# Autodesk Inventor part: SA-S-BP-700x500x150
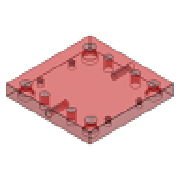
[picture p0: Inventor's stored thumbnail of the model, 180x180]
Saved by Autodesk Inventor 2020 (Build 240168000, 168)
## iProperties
Created: 2019-01
Part Number: SA-S-BP-700x500x150
Material: S 55 C
Description: Core Plate
Document SubType Name: Modeling
Designer: LENOVO-CADCIM
Standard Revision: 1
Manufacturer: FUTABA
Language: en-US
Size Designation: 700x500x150
Categories: <MemberInstance><Categories><Category DisplayName="Mold" InternalName="349578f2-f4d4-4954-8c09-8e99297a61c0" Mnemonic="MOLD"><Category DisplayName="Mold Plates"
Density: 7.85 g/cm^3
Appearance: Dark Red
IsCustomPart: 1
Author: LENOVO-CADCIM
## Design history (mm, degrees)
sketch "Sketch1"
  geometry: L1 (-250, 350)-(250, 350); L2 (250, 350)-(250, -350); L3 (250, -350)-(-250, -350); L4 (-250, -350)-(-250, 350); 7 further points
  constraints: 8 end point, 2 horizontal alignment, 2 midpoint, 2 parallel, 1 horizontal, 1 perpendicular, 1 vertical alignment
  dimensions: "d123" = 500 distance between parallel lines of L2 L4 (= W_); "d124" = 700 distance between parallel lines of L3 L1 (= L); "d125" = 317 vertical distance of point (0, 0) point (-128, 317) (= 0.5 x RP_L); "d126" = 128 horizontal distance of point (0, 0) point (-128, 317) (= 0.5 x RP_W); "d127" = 207 horizontal distance of point (0, 0) point (-207, 307) (= 0.5 x GP_W); "d128" = 307 vertical distance of point (0, 0) point (-207, 307) (= 0.5 x GP_L); "d129" = 205 horizontal distance of point (0, 0) point (-205, 243) (= 0.5 x S1_W); "d130" = 243 vertical distance of point (0, 0) point (-205, 243) (= 0.5 x S1_L); "d140" = 207 horizontal distance of point (207, 307) point (0, 0) (= 0.5 x GP_W)
extrude "Extrusion1" new body sketch "Sketch1" distance "d20" = 150 (= H_); taper "d30" = 0 deg
feature "Sculpt3"
body "Solid1"
sketch "Sketch2"
  geometry: L1 (500, 0)-(0, 0) reference; 3 further points
  constraints: 1 midpoint, 1 vertical alignment
  dimensions: "d186" = 75 distance from line of L1 point (250, 75) (= 0.5 x H_)
hole "Hole1" sketch "Sketch2" diameter "d104" = 31.67; stored, may be unused: countersink angle "d108" = 90 deg, drill point angle "d110" = 118 deg; dims "d105" = 59 (= le), "d106" = 46 (= GP_d2), "d107" = 10 (= GP_k), "d109" = 82 (= ke)
sketch "Sketch3"
  geometry: L1 (0, 0)-(500, 0) reference; 3 further points
  constraints: 1 midpoint, 1 vertical alignment
  dimensions: "d187" = 75 distance from line of point (250, -75) L1 (= 0.5 x H_)
hole "Hole2" sketch "Sketch3" diameter "d113" = 31.67; stored, may be unused: countersink angle "d117" = 90 deg, drill point angle "d119" = 118 deg; dims "d114" = 59 (= le), "d115" = 46 (= GP_d2), "d116" = 10 (= GP_k), "d118" = 82 (= ke)
hole "Hole3" sketch "Sketch1" diameter "d131" = 13.835; stored, may be unused: countersink angle "d135" = 90 deg, drill point angle "d137" = 118 deg; dims "d132" = 20 (= H_l), "d133" = 4, "d134" = 2, "d136" = 30 (= H_u)
pattern_linear "Rectangular Pattern1" dims "d164" = 243 (computed from S1_L, Ns), "d167" = 410 (computed from S1_W, Nw)
hole "Hole4" sketch "Sketch1" diameter "d141" = 40 (= GP_d1); stored, may be unused: countersink angle "d145" = 90 deg, drill point angle "d147" = 0 deg; dims "d142" = 6, "d143" = 46 (= GP_d2), "d144" = 10 (= GP_k), "d146" = 150 (= H_)
pattern_linear "Rectangular Pattern2" dims "d170" = 614 (computed from GP_L, Nl)
hole "Hole5" sketch "Sketch1" diameter "d148" = 40 (= GP_d1); stored, may be unused: countersink angle "d152" = 90 deg, drill point angle "d154" = 0 deg; dims "d149" = 6, "d150" = 46 (= GP_d2), "d151" = 10 (= GP_k), "d153" = 150 (= H_)
pattern_linear "Rectangular Pattern3" dims "d173" = 612 (computed from GP_L2, GP_L1, Nl)
hole "Hole6" sketch "Sketch1" diameter "d155" = 30 (= RP_dt); stored, may be unused: countersink angle "d159" = 90 deg, drill point angle "d161" = 0 deg; dims "d156" = 6, "d157" = 46 (= GP_d2), "d158" = 10 (= GP_k), "d160" = 150 (= H_)
pattern_linear "Rectangular Pattern4" dims "d176" = 634 (computed from RP_L, Nl), "d179" = 256 (computed from RP_W, Nw)
chamfer "Chamfer1" distance "d180" = 0.5; stored, may be unused: second distance "d181" = 2, angle "d182" = 45 deg
feature "Surface3"
body "Srf3"
other parameters: "L" = 700 [user parameter; used in 1 equation term], "W_" = 500 [user parameter; used in 3 equation terms], "H_" = 150 [user parameter; used in 8 equation terms], "GP_W" = 414 [user parameter; used in 2 equation terms], "GP_d1" = 40 [user parameter; used in 2 equation terms], "GP_d2" = 46 [user parameter; used in 5 equation terms], "GP_k" = 10 [user parameter; used in 5 equation terms], "S1_L" = 486 [user parameter; used in 2 equation terms], "GP_L1" = 307 [user parameter; used in 1 equation term], "GP_L2" = 305 [user parameter; used in 1 equation term], "RP_L" = 634 [user parameter; used in 2 equation terms], "RP_W" = 256 [user parameter; used in 2 equation terms], "RP_dt" = 30 [user parameter; used in 1 equation term], "GP_L" = 614 [user parameter; used in 2 equation terms], "d102" = 75 (= 0.5 x H_), "d112" = 75 (= 0.5 x H_), "le" = 59 [user parameter; used in 2 equation terms], "ke" = 82 [user parameter; used in 2 equation terms], "H_l" = 20 [user parameter; used in 1 equation term], "H_u" = 30 [user parameter; used in 1 equation term]
